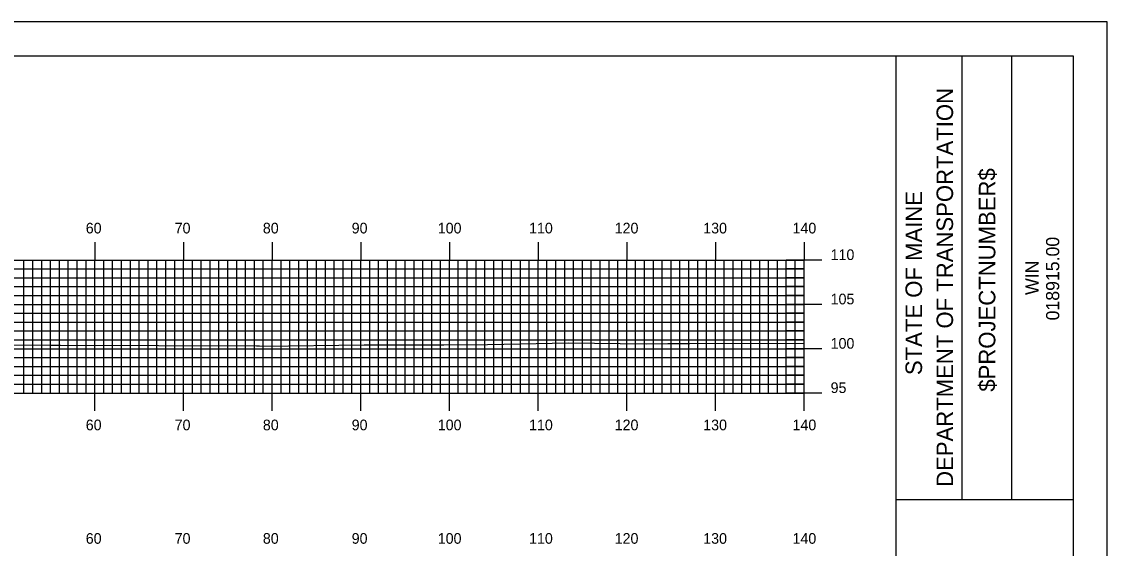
# Model space of a CAD drawing. Extents: x 1778712 to 1779055, y 442591 to 442811.
# Drawn here: x 1778929.6 to 1779052, y 442751.2 to 442810.5 of the extents above; entities that cross this region are included whole.
import ezdxf

# ---------------------------------------------------------------- set-up
doc = ezdxf.new("R2010")
doc.units = 0
for name, color, linetype in [('BORDER', 7, 'Continuous'), ('H_V ANNOTATION', 7, 'Continuous'), ('MAJOR', 7, 'Continuous'), ('MINOR', 7, 'Continuous'), ('PLOT BOUNDARY', 7, 'Continuous'), ('S_Roadway_Centerline', 7, 'Continuous')]:
    doc.layers.add(name, color=color, linetype=linetype)

msp = doc.modelspace()

# ---------------------------------------------------------------- linework, layer by layer
at = {"layer": 'BORDER'}
for p, q in [((1779028.22, 442596.67), (1779028.22, 442806.67)), ((1779035.67, 442756.66), (1779035.67, 442806.66)), ((1779041.26, 442756.66), (1779041.26, 442806.66)), ((1779028.22, 442756.65), (1779048.22, 442756.65))]:
    msp.add_line(p, q, dxfattribs=at)
msp.add_lwpolyline([(1778728.22, 442596.67), (1779048.22, 442596.67), (1779048.22, 442806.67), (1778728.22, 442806.67)], close=True, dxfattribs=at)
at = {"layer": 'MAJOR'}
for p, q in [((1778937.82, 442785.67), (1778937.82, 442783.67)), ((1778947.82, 442785.67), (1778947.82, 442783.67)), ((1778957.82, 442785.67), (1778957.82, 442783.67)), ((1778967.82, 442785.67), (1778967.82, 442783.67)), ((1778977.82, 442785.67), (1778977.82, 442783.67)), ((1778987.82, 442785.67), (1778987.82, 442783.67)), ((1778997.82, 442785.67), (1778997.82, 442783.67)), ((1779007.82, 442785.67), (1779007.82, 442783.67)), ((1779017.82, 442785.67), (1779017.82, 442783.67)), ((1778737.82, 442783.67), (1779017.82, 442783.67)), ((1778737.82, 442783.67), (1779017.82, 442783.67)), ((1778937.82, 442768.67), (1778937.82, 442783.67)), ((1778947.82, 442768.67), (1778947.82, 442783.67)), ((1778957.82, 442768.67), (1778957.82, 442783.67)), ((1778967.82, 442768.67), (1778967.82, 442783.67)), ((1778977.82, 442768.67), (1778977.82, 442783.67)), ((1778987.82, 442768.67), (1778987.82, 442783.67)), ((1778997.82, 442768.67), (1778997.82, 442783.67)), ((1779007.82, 442768.67), (1779007.82, 442783.67)), ((1779019.82, 442783.67), (1779015.81, 442783.67)), ((1779017.82, 442768.67), (1779017.82, 442783.67)), ((1779017.82, 442768.67), (1779017.82, 442783.67)), ((1778737.82, 442778.67), (1779017.82, 442778.67)), ((1779019.82, 442778.67), (1779015.81, 442778.67)), ((1778737.82, 442773.67), (1779017.82, 442773.67)), ((1779019.82, 442773.67), (1779015.81, 442773.67)), ((1778737.82, 442768.67), (1779017.82, 442768.67)), ((1778737.82, 442768.67), (1779017.82, 442768.67)), ((1778937.82, 442766.66), (1778937.82, 442768.67)), ((1778947.82, 442766.66), (1778947.82, 442768.67)), ((1778957.82, 442766.66), (1778957.82, 442768.67)), ((1778967.82, 442766.66), (1778967.82, 442768.67)), ((1778977.82, 442766.66), (1778977.82, 442768.67)), ((1778987.82, 442766.66), (1778987.82, 442768.67)), ((1778997.82, 442766.66), (1778997.82, 442768.67)), ((1779007.82, 442766.66), (1779007.82, 442768.67)), ((1779019.82, 442768.67), (1779015.81, 442768.67)), ((1779017.82, 442766.66), (1779017.82, 442768.67))]:
    msp.add_line(p, q, dxfattribs=at)
at = {"layer": 'MINOR'}
for p, q in [((1778929.82, 442768.67), (1778929.82, 442783.67)), ((1778930.82, 442768.67), (1778930.82, 442783.67)), ((1778931.82, 442768.67), (1778931.82, 442783.67)), ((1778932.82, 442768.67), (1778932.82, 442783.67)), ((1778933.82, 442768.67), (1778933.82, 442783.67)), ((1778934.82, 442768.67), (1778934.82, 442783.67)), ((1778935.82, 442768.67), (1778935.82, 442783.67)), ((1778936.82, 442768.67), (1778936.82, 442783.67)), ((1778938.82, 442768.67), (1778938.82, 442783.67)), ((1778939.82, 442768.67), (1778939.82, 442783.67)), ((1778940.82, 442768.67), (1778940.82, 442783.67)), ((1778941.82, 442768.67), (1778941.82, 442783.67)), ((1778942.82, 442768.67), (1778942.82, 442783.67)), ((1778943.82, 442768.67), (1778943.82, 442783.67)), ((1778944.82, 442768.67), (1778944.82, 442783.67)), ((1778945.82, 442768.67), (1778945.82, 442783.67)), ((1778946.82, 442768.67), (1778946.82, 442783.67)), ((1778948.82, 442768.67), (1778948.82, 442783.67)), ((1778949.82, 442768.67), (1778949.82, 442783.67)), ((1778950.82, 442768.67), (1778950.82, 442783.67)), ((1778951.82, 442768.67), (1778951.82, 442783.67)), ((1778952.82, 442768.67), (1778952.82, 442783.67)), ((1778953.82, 442768.67), (1778953.82, 442783.67)), ((1778954.82, 442768.67), (1778954.82, 442783.67)), ((1778955.82, 442768.67), (1778955.82, 442783.67)), ((1778956.82, 442768.67), (1778956.82, 442783.67)), ((1778958.82, 442768.67), (1778958.82, 442783.67)), ((1778959.82, 442768.67), (1778959.82, 442783.67)), ((1778960.82, 442768.67), (1778960.82, 442783.67)), ((1778961.82, 442768.67), (1778961.82, 442783.67)), ((1778962.82, 442768.67), (1778962.82, 442783.67)), ((1778963.82, 442768.67), (1778963.82, 442783.67)), ((1778964.82, 442768.67), (1778964.82, 442783.67)), ((1778965.82, 442768.67), (1778965.82, 442783.67)), ((1778966.82, 442768.67), (1778966.82, 442783.67)), ((1778968.82, 442768.67), (1778968.82, 442783.67)), ((1778969.82, 442768.67), (1778969.82, 442783.67)), ((1778970.82, 442768.67), (1778970.82, 442783.67)), ((1778971.82, 442768.67), (1778971.82, 442783.67)), ((1778972.82, 442768.67), (1778972.82, 442783.67)), ((1778973.82, 442768.67), (1778973.82, 442783.67)), ((1778974.82, 442768.67), (1778974.82, 442783.67)), ((1778975.82, 442768.67), (1778975.82, 442783.67)), ((1778976.82, 442768.67), (1778976.82, 442783.67)), ((1778978.82, 442768.67), (1778978.82, 442783.67)), ((1778979.82, 442768.67), (1778979.82, 442783.67)), ((1778980.82, 442768.67), (1778980.82, 442783.67)), ((1778981.82, 442768.67), (1778981.82, 442783.67)), ((1778982.82, 442768.67), (1778982.82, 442783.67)), ((1778983.82, 442768.67), (1778983.82, 442783.67)), ((1778984.82, 442768.67), (1778984.82, 442783.67)), ((1778985.82, 442768.67), (1778985.82, 442783.67)), ((1778986.82, 442768.67), (1778986.82, 442783.67)), ((1778988.82, 442768.67), (1778988.82, 442783.67)), ((1778989.82, 442768.67), (1778989.82, 442783.67)), ((1778990.82, 442768.67), (1778990.82, 442783.67)), ((1778991.82, 442768.67), (1778991.82, 442783.67)), ((1778992.82, 442768.67), (1778992.82, 442783.67)), ((1778993.82, 442768.67), (1778993.82, 442783.67)), ((1778994.82, 442768.67), (1778994.82, 442783.67)), ((1778995.82, 442768.67), (1778995.82, 442783.67)), ((1778996.82, 442768.67), (1778996.82, 442783.67)), ((1778998.82, 442768.67), (1778998.82, 442783.67)), ((1778999.82, 442768.67), (1778999.82, 442783.67)), ((1779000.82, 442768.67), (1779000.82, 442783.67)), ((1779001.82, 442768.67), (1779001.82, 442783.67)), ((1779002.82, 442768.67), (1779002.82, 442783.67)), ((1779003.82, 442768.67), (1779003.82, 442783.67)), ((1779004.82, 442768.67), (1779004.82, 442783.67)), ((1779005.82, 442768.67), (1779005.82, 442783.67)), ((1779006.82, 442768.67), (1779006.82, 442783.67)), ((1779008.82, 442768.67), (1779008.82, 442783.67)), ((1779009.82, 442768.67), (1779009.82, 442783.67)), ((1779010.82, 442768.67), (1779010.82, 442783.67)), ((1779011.82, 442768.67), (1779011.82, 442783.67)), ((1779012.82, 442768.67), (1779012.82, 442783.67)), ((1779013.82, 442768.67), (1779013.82, 442783.67)), ((1779014.82, 442768.67), (1779014.82, 442783.67)), ((1779015.82, 442768.67), (1779015.82, 442783.67)), ((1779016.82, 442768.67), (1779016.82, 442783.67)), ((1778737.82, 442782.67), (1779017.82, 442782.67)), ((1778737.82, 442781.67), (1779017.82, 442781.67)), ((1779017.82, 442782.67), (1779015.81, 442782.67)), ((1779017.82, 442781.67), (1779015.81, 442781.67)), ((1778737.82, 442780.67), (1779017.82, 442780.67)), ((1779017.82, 442780.67), (1779015.81, 442780.67)), ((1778737.82, 442779.67), (1779017.82, 442779.67)), ((1779017.82, 442779.67), (1779015.81, 442779.67)), ((1778737.82, 442777.67), (1779017.82, 442777.67)), ((1779017.82, 442777.67), (1779015.81, 442777.67)), ((1778737.82, 442776.67), (1779017.82, 442776.67)), ((1778737.82, 442775.67), (1779017.82, 442775.67)), ((1779017.82, 442776.67), (1779015.81, 442776.67)), ((1779017.82, 442775.67), (1779015.81, 442775.67)), ((1778737.82, 442774.67), (1779017.82, 442774.67)), ((1779017.82, 442774.67), (1779015.81, 442774.67)), ((1778737.82, 442772.67), (1779017.82, 442772.67)), ((1779017.82, 442772.67), (1779015.81, 442772.67)), ((1778737.82, 442771.67), (1779017.82, 442771.67)), ((1778737.82, 442770.67), (1779017.82, 442770.67)), ((1779017.82, 442771.67), (1779015.81, 442771.67)), ((1779017.82, 442770.67), (1779015.81, 442770.67)), ((1778737.82, 442769.67), (1779017.82, 442769.67)), ((1779017.82, 442769.67), (1779015.81, 442769.67))]:
    msp.add_line(p, q, dxfattribs=at)
at = {"layer": 'PLOT BOUNDARY'}
msp.add_lwpolyline([(1778712.03, 442590.55), (1779052.03, 442590.55), (1779052.03, 442810.55), (1778712.03, 442810.55)], close=True, dxfattribs=at)
at = {"layer": 'S_Roadway_Centerline'}
msp.add_lwpolyline([(1778921.19, 442774.1), (1778932.72, 442774.05), (1778933.93, 442774.05), (1778956.07, 442773.98), (1778956.4, 442773.98), (1778956.81, 442773.97), (1778968.18, 442774.12), (1778977.17, 442774.1), (1778982.1, 442774.15), (1778991.23, 442774.33), (1779000.02, 442774.23), (1779002.47, 442774.24), (1779004.95, 442774.26), (1779017.82, 442774.29)], dxfattribs=at)

# ---------------------------------------------------------------- texts
at = {"layer": 'BORDER'}
for s, height, p in [('DEPARTMENT OF TRANSPORTATION', 1.8635, (1779034.63, 442758.08)), ('$PROJECTNUMBER$', 1.8635, (1779039.4, 442768.82)), ('STATE OF MAINE', 1.8635, (1779031.13, 442770.69)), ('018915.00', 1.491, (1779046.61, 442776.86)), ('WIN', 1.491, (1779044.29, 442779.73))]:
    msp.add_text(s, height=height, rotation=90, dxfattribs=at).set_placement(p)
at = {"layer": 'H_V ANNOTATION'}
for s, p in [('60', (1778936.79, 442786.67)), ('70', (1778946.82, 442786.67)), ('80', (1778956.77, 442786.67)), ('90', (1778966.79, 442786.67)), ('100', (1778976.5, 442786.67)), ('110', (1778986.8, 442786.67)), ('120', (1778996.46, 442786.67)), ('130', (1779006.45, 442786.67)), ('140', (1779016.52, 442786.67)), ('110', (1779020.82, 442783.67)), ('105', (1779020.82, 442778.67)), ('100', (1779020.82, 442773.67)), ('95', (1779020.82, 442768.67)), ('60', (1778936.79, 442764.47)), ('70', (1778946.82, 442764.47)), ('80', (1778956.77, 442764.47)), ('90', (1778966.79, 442764.47)), ('100', (1778976.5, 442764.47)), ('110', (1778986.8, 442764.47)), ('120', (1778996.46, 442764.47)), ('130', (1779006.45, 442764.47)), ('140', (1779016.52, 442764.47)), ('60', (1778936.79, 442751.67)), ('70', (1778946.82, 442751.67)), ('80', (1778956.77, 442751.67)), ('90', (1778966.79, 442751.67)), ('100', (1778976.5, 442751.67)), ('110', (1778986.8, 442751.67)), ('120', (1778996.46, 442751.67)), ('130', (1779006.45, 442751.67)), ('140', (1779016.52, 442751.67))]:
    msp.add_text(s, height=1.2, dxfattribs=at).set_placement(p)

doc.saveas('drawing.dxf')
